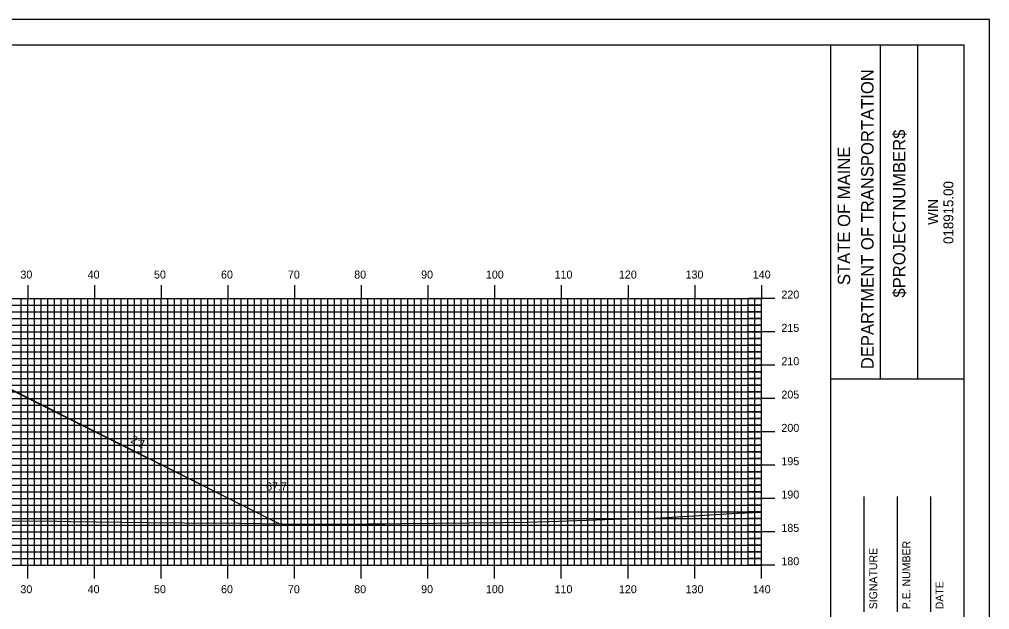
# Model space of a CAD drawing. Extents: x 1810193 to 1810536, y 442591 to 442811.
# Drawn here: x 1810387.6 to 1810533.1, y 442722 to 442810.5 of the extents above; entities that cross this region are included whole.
import ezdxf

# ---------------------------------------------------------------- set-up
doc = ezdxf.new("R2010")
doc.units = 0
for name, color, linetype in [('ANNOTATION', 7, 'Continuous'), ('BORDER', 7, 'Continuous'), ('D_Roadway_Centerline', 7, 'Continuous'), ('D_Roadway_SlopeLines', 7, 'Continuous'), ('D_Text_Standard', 7, 'Continuous'), ('H_V ANNOTATION', 7, 'Continuous'), ('MAJOR', 7, 'Continuous'), ('MINOR', 7, 'Continuous'), ('PLOT BOUNDARY', 7, 'Continuous'), ('S_Roadway_Centerline', 7, 'Continuous')]:
    doc.layers.add(name, color=color, linetype=linetype)

msp = doc.modelspace()

# ---------------------------------------------------------------- linework, layer by layer
at = {"layer": 'BORDER'}
for p, q in [((1810509.26, 442596.67), (1810509.26, 442806.67)), ((1810516.72, 442756.66), (1810516.72, 442806.66)), ((1810522.31, 442756.66), (1810522.31, 442806.66)), ((1810509.27, 442756.65), (1810529.26, 442756.65)), ((1810514.26, 442721.67), (1810514.26, 442738.97)), ((1810519.26, 442721.67), (1810519.26, 442738.97)), ((1810524.26, 442721.67), (1810524.26, 442738.97))]:
    msp.add_line(p, q, dxfattribs=at)
msp.add_lwpolyline([(1810209.26, 442596.67), (1810529.26, 442596.67), (1810529.26, 442806.67), (1810209.26, 442806.67)], close=True, dxfattribs=at)
at = {"layer": 'D_Roadway_Centerline'}
msp.add_lwpolyline([(1810289.54, 442735.57), (1810330.66, 442756.12), (1810335.86, 442758.73), (1810338.86, 442758.79), (1810346.86, 442758.95), (1810358.86, 442758.37), (1810370.86, 442757.79), (1810378.86, 442757.41), (1810381.86, 442757.27), (1810387.39, 442754.5), (1810426.61, 442734.89)], dxfattribs=at)
at = {"layer": 'D_Roadway_SlopeLines'}
msp.add_lwpolyline([(1810381.86, 442757.27), (1810426.61, 442734.89)], dxfattribs=at)
at = {"layer": 'MAJOR'}
for p, q in [((1810388.86, 442770.67), (1810388.86, 442768.67)), ((1810398.86, 442770.67), (1810398.86, 442768.67)), ((1810408.86, 442770.67), (1810408.86, 442768.67)), ((1810418.86, 442770.67), (1810418.86, 442768.67)), ((1810428.86, 442770.67), (1810428.86, 442768.67)), ((1810438.86, 442770.67), (1810438.86, 442768.67)), ((1810448.86, 442770.67), (1810448.86, 442768.67)), ((1810458.86, 442770.67), (1810458.86, 442768.67)), ((1810468.86, 442770.67), (1810468.86, 442768.67)), ((1810478.86, 442770.67), (1810478.86, 442768.67)), ((1810488.86, 442770.67), (1810488.86, 442768.67)), ((1810498.86, 442770.67), (1810498.86, 442768.67)), ((1810218.86, 442768.67), (1810498.86, 442768.67)), ((1810218.86, 442768.67), (1810498.86, 442768.67)), ((1810388.86, 442728.67), (1810388.86, 442768.67)), ((1810398.86, 442728.67), (1810398.86, 442768.67)), ((1810408.86, 442728.67), (1810408.86, 442768.67)), ((1810418.86, 442728.67), (1810418.86, 442768.67)), ((1810428.86, 442728.67), (1810428.86, 442768.67)), ((1810438.86, 442728.67), (1810438.86, 442768.67)), ((1810448.86, 442728.67), (1810448.86, 442768.67)), ((1810458.86, 442728.67), (1810458.86, 442768.67)), ((1810468.86, 442728.67), (1810468.86, 442768.67)), ((1810478.86, 442728.67), (1810478.86, 442768.67)), ((1810488.86, 442728.67), (1810488.86, 442768.67)), ((1810500.87, 442768.67), (1810496.86, 442768.67)), ((1810498.86, 442728.67), (1810498.86, 442768.67)), ((1810498.86, 442728.67), (1810498.86, 442768.67)), ((1810218.86, 442763.67), (1810498.86, 442763.67)), ((1810500.87, 442763.67), (1810496.86, 442763.67)), ((1810218.86, 442758.67), (1810498.86, 442758.67)), ((1810500.87, 442758.67), (1810496.86, 442758.67)), ((1810218.86, 442753.67), (1810498.86, 442753.67)), ((1810500.87, 442753.67), (1810496.86, 442753.67)), ((1810218.86, 442748.67), (1810498.86, 442748.67)), ((1810500.87, 442748.67), (1810496.86, 442748.67)), ((1810218.86, 442743.67), (1810498.86, 442743.67)), ((1810500.87, 442743.67), (1810496.86, 442743.67)), ((1810218.86, 442738.67), (1810498.86, 442738.67)), ((1810500.87, 442738.67), (1810496.86, 442738.67)), ((1810218.86, 442733.67), (1810498.86, 442733.67)), ((1810500.87, 442733.67), (1810496.86, 442733.67)), ((1810218.86, 442728.67), (1810498.86, 442728.67)), ((1810218.86, 442728.67), (1810498.86, 442728.67)), ((1810388.86, 442726.66), (1810388.86, 442728.67)), ((1810398.86, 442726.66), (1810398.86, 442728.67)), ((1810408.86, 442726.66), (1810408.86, 442728.67)), ((1810418.86, 442726.66), (1810418.86, 442728.67)), ((1810428.86, 442726.66), (1810428.86, 442728.67)), ((1810438.86, 442726.66), (1810438.86, 442728.67)), ((1810448.86, 442726.66), (1810448.86, 442728.67)), ((1810458.86, 442726.66), (1810458.86, 442728.67)), ((1810468.86, 442726.66), (1810468.86, 442728.67)), ((1810478.86, 442726.66), (1810478.86, 442728.67)), ((1810488.86, 442726.66), (1810488.86, 442728.67)), ((1810500.87, 442728.67), (1810496.86, 442728.67)), ((1810498.86, 442726.66), (1810498.86, 442728.67))]:
    msp.add_line(p, q, dxfattribs=at)
at = {"layer": 'MINOR'}
for p, q in [((1810387.86, 442728.67), (1810387.86, 442768.67)), ((1810389.86, 442728.67), (1810389.86, 442768.67)), ((1810390.86, 442728.67), (1810390.86, 442768.67)), ((1810391.86, 442728.67), (1810391.86, 442768.67)), ((1810392.86, 442728.67), (1810392.86, 442768.67)), ((1810393.86, 442728.67), (1810393.86, 442768.67)), ((1810394.86, 442728.67), (1810394.86, 442768.67)), ((1810395.86, 442728.67), (1810395.86, 442768.67)), ((1810396.86, 442728.67), (1810396.86, 442768.67)), ((1810397.86, 442728.67), (1810397.86, 442768.67)), ((1810399.86, 442728.67), (1810399.86, 442768.67)), ((1810400.86, 442728.67), (1810400.86, 442768.67)), ((1810401.86, 442728.67), (1810401.86, 442768.67)), ((1810402.86, 442728.67), (1810402.86, 442768.67)), ((1810403.86, 442728.67), (1810403.86, 442768.67)), ((1810404.86, 442728.67), (1810404.86, 442768.67)), ((1810405.86, 442728.67), (1810405.86, 442768.67)), ((1810406.86, 442728.67), (1810406.86, 442768.67)), ((1810407.86, 442728.67), (1810407.86, 442768.67)), ((1810409.86, 442728.67), (1810409.86, 442768.67)), ((1810410.86, 442728.67), (1810410.86, 442768.67)), ((1810411.86, 442728.67), (1810411.86, 442768.67)), ((1810412.86, 442728.67), (1810412.86, 442768.67)), ((1810413.86, 442728.67), (1810413.86, 442768.67)), ((1810414.86, 442728.67), (1810414.86, 442768.67)), ((1810415.86, 442728.67), (1810415.86, 442768.67)), ((1810416.86, 442728.67), (1810416.86, 442768.67)), ((1810417.86, 442728.67), (1810417.86, 442768.67)), ((1810419.86, 442728.67), (1810419.86, 442768.67)), ((1810420.86, 442728.67), (1810420.86, 442768.67)), ((1810421.86, 442728.67), (1810421.86, 442768.67)), ((1810422.86, 442728.67), (1810422.86, 442768.67)), ((1810423.86, 442728.67), (1810423.86, 442768.67)), ((1810424.86, 442728.67), (1810424.86, 442768.67)), ((1810425.86, 442728.67), (1810425.86, 442768.67)), ((1810426.86, 442728.67), (1810426.86, 442768.67)), ((1810427.86, 442728.67), (1810427.86, 442768.67)), ((1810429.86, 442728.67), (1810429.86, 442768.67)), ((1810430.86, 442728.67), (1810430.86, 442768.67)), ((1810431.86, 442728.67), (1810431.86, 442768.67)), ((1810432.86, 442728.67), (1810432.86, 442768.67)), ((1810433.86, 442728.67), (1810433.86, 442768.67)), ((1810434.86, 442728.67), (1810434.86, 442768.67)), ((1810435.86, 442728.67), (1810435.86, 442768.67)), ((1810436.86, 442728.67), (1810436.86, 442768.67)), ((1810437.86, 442728.67), (1810437.86, 442768.67)), ((1810439.86, 442728.67), (1810439.86, 442768.67)), ((1810440.86, 442728.67), (1810440.86, 442768.67)), ((1810441.86, 442728.67), (1810441.86, 442768.67)), ((1810442.86, 442728.67), (1810442.86, 442768.67)), ((1810443.86, 442728.67), (1810443.86, 442768.67)), ((1810444.86, 442728.67), (1810444.86, 442768.67)), ((1810445.86, 442728.67), (1810445.86, 442768.67)), ((1810446.86, 442728.67), (1810446.86, 442768.67)), ((1810447.86, 442728.67), (1810447.86, 442768.67)), ((1810449.86, 442728.67), (1810449.86, 442768.67)), ((1810450.86, 442728.67), (1810450.86, 442768.67)), ((1810451.86, 442728.67), (1810451.86, 442768.67)), ((1810452.86, 442728.67), (1810452.86, 442768.67)), ((1810453.86, 442728.67), (1810453.86, 442768.67)), ((1810454.86, 442728.67), (1810454.86, 442768.67)), ((1810455.86, 442728.67), (1810455.86, 442768.67)), ((1810456.86, 442728.67), (1810456.86, 442768.67)), ((1810457.86, 442728.67), (1810457.86, 442768.67)), ((1810459.86, 442728.67), (1810459.86, 442768.67)), ((1810460.86, 442728.67), (1810460.86, 442768.67)), ((1810461.86, 442728.67), (1810461.86, 442768.67)), ((1810462.86, 442728.67), (1810462.86, 442768.67)), ((1810463.86, 442728.67), (1810463.86, 442768.67)), ((1810464.86, 442728.67), (1810464.86, 442768.67)), ((1810465.86, 442728.67), (1810465.86, 442768.67)), ((1810466.86, 442728.67), (1810466.86, 442768.67)), ((1810467.86, 442728.67), (1810467.86, 442768.67)), ((1810469.86, 442728.67), (1810469.86, 442768.67)), ((1810470.86, 442728.67), (1810470.86, 442768.67)), ((1810471.86, 442728.67), (1810471.86, 442768.67)), ((1810472.86, 442728.67), (1810472.86, 442768.67)), ((1810473.86, 442728.67), (1810473.86, 442768.67)), ((1810474.86, 442728.67), (1810474.86, 442768.67)), ((1810475.86, 442728.67), (1810475.86, 442768.67)), ((1810476.86, 442728.67), (1810476.86, 442768.67)), ((1810477.86, 442728.67), (1810477.86, 442768.67)), ((1810479.86, 442728.67), (1810479.86, 442768.67)), ((1810480.86, 442728.67), (1810480.86, 442768.67)), ((1810481.86, 442728.67), (1810481.86, 442768.67)), ((1810482.86, 442728.67), (1810482.86, 442768.67)), ((1810483.86, 442728.67), (1810483.86, 442768.67)), ((1810484.86, 442728.67), (1810484.86, 442768.67)), ((1810485.86, 442728.67), (1810485.86, 442768.67)), ((1810486.86, 442728.67), (1810486.86, 442768.67)), ((1810487.86, 442728.67), (1810487.86, 442768.67)), ((1810489.86, 442728.67), (1810489.86, 442768.67)), ((1810490.86, 442728.67), (1810490.86, 442768.67)), ((1810491.86, 442728.67), (1810491.86, 442768.67)), ((1810492.86, 442728.67), (1810492.86, 442768.67)), ((1810493.86, 442728.67), (1810493.86, 442768.67)), ((1810494.86, 442728.67), (1810494.86, 442768.67)), ((1810495.86, 442728.67), (1810495.86, 442768.67)), ((1810496.86, 442728.67), (1810496.86, 442768.67)), ((1810497.86, 442728.67), (1810497.86, 442768.67)), ((1810218.86, 442767.67), (1810498.86, 442767.67)), ((1810498.86, 442767.67), (1810496.86, 442767.67)), ((1810218.86, 442766.67), (1810498.86, 442766.67)), ((1810218.86, 442765.67), (1810498.86, 442765.67)), ((1810498.86, 442766.67), (1810496.86, 442766.67)), ((1810498.86, 442765.67), (1810496.86, 442765.67)), ((1810218.86, 442764.67), (1810498.86, 442764.67)), ((1810498.86, 442764.67), (1810496.86, 442764.67)), ((1810218.86, 442762.67), (1810498.86, 442762.67)), ((1810498.86, 442762.67), (1810496.86, 442762.67)), ((1810218.86, 442761.67), (1810498.86, 442761.67)), ((1810498.86, 442761.67), (1810496.86, 442761.67)), ((1810218.86, 442760.67), (1810498.86, 442760.67)), ((1810498.86, 442760.67), (1810496.86, 442760.67)), ((1810218.86, 442759.67), (1810498.86, 442759.67)), ((1810498.86, 442759.67), (1810496.86, 442759.67)), ((1810218.86, 442757.67), (1810498.86, 442757.67)), ((1810498.86, 442757.67), (1810496.86, 442757.67)), ((1810218.86, 442756.67), (1810498.86, 442756.67)), ((1810218.86, 442755.67), (1810498.86, 442755.67)), ((1810498.86, 442756.67), (1810496.86, 442756.67)), ((1810498.86, 442755.67), (1810496.86, 442755.67)), ((1810218.86, 442754.67), (1810498.86, 442754.67)), ((1810498.86, 442754.67), (1810496.86, 442754.67)), ((1810218.86, 442752.67), (1810498.86, 442752.67)), ((1810498.86, 442752.67), (1810496.86, 442752.67)), ((1810218.86, 442751.67), (1810498.86, 442751.67)), ((1810498.86, 442751.67), (1810496.86, 442751.67)), ((1810218.86, 442750.67), (1810498.86, 442750.67)), ((1810218.86, 442749.67), (1810498.86, 442749.67)), ((1810498.86, 442750.67), (1810496.86, 442750.67)), ((1810498.86, 442749.67), (1810496.86, 442749.67)), ((1810218.86, 442747.67), (1810498.86, 442747.67)), ((1810218.86, 442746.67), (1810498.86, 442746.67)), ((1810498.86, 442747.67), (1810496.86, 442747.67)), ((1810498.86, 442746.67), (1810496.86, 442746.67)), ((1810218.86, 442745.67), (1810498.86, 442745.67)), ((1810498.86, 442745.67), (1810496.86, 442745.67)), ((1810218.86, 442744.67), (1810498.86, 442744.67)), ((1810498.86, 442744.67), (1810496.86, 442744.67)), ((1810218.86, 442742.67), (1810498.86, 442742.67)), ((1810498.86, 442742.67), (1810496.86, 442742.67)), ((1810218.86, 442741.67), (1810498.86, 442741.67)), ((1810498.86, 442741.67), (1810496.86, 442741.67)), ((1810218.86, 442740.67), (1810498.86, 442740.67)), ((1810218.86, 442739.67), (1810498.86, 442739.67)), ((1810498.86, 442740.67), (1810496.86, 442740.67)), ((1810498.86, 442739.67), (1810496.86, 442739.67)), ((1810218.86, 442737.67), (1810498.86, 442737.67)), ((1810218.86, 442736.67), (1810498.86, 442736.67)), ((1810498.86, 442737.67), (1810496.86, 442737.67)), ((1810498.86, 442736.67), (1810496.86, 442736.67)), ((1810218.86, 442735.67), (1810498.86, 442735.67)), ((1810498.86, 442735.67), (1810496.86, 442735.67)), ((1810218.86, 442734.67), (1810498.86, 442734.67)), ((1810498.86, 442734.67), (1810496.86, 442734.67)), ((1810218.86, 442732.67), (1810498.86, 442732.67)), ((1810498.86, 442732.67), (1810496.86, 442732.67)), ((1810218.86, 442731.67), (1810498.86, 442731.67)), ((1810218.86, 442730.67), (1810498.86, 442730.67)), ((1810498.86, 442731.67), (1810496.86, 442731.67)), ((1810498.86, 442730.67), (1810496.86, 442730.67)), ((1810218.86, 442729.67), (1810498.86, 442729.67)), ((1810498.86, 442729.67), (1810496.86, 442729.67))]:
    msp.add_line(p, q, dxfattribs=at)
at = {"layer": 'PLOT BOUNDARY'}
msp.add_lwpolyline([(1810193.08, 442590.55), (1810533.08, 442590.55), (1810533.08, 442810.55), (1810193.08, 442810.55)], close=True, dxfattribs=at)
at = {"layer": 'S_Roadway_Centerline'}
msp.add_lwpolyline([(1810372.66, 442735.45), (1810393.27, 442735.26), (1810395.17, 442735.25), (1810395.31, 442735.24), (1810406.69, 442735.1), (1810417.98, 442734.99), (1810419.4, 442735.01), (1810420.68, 442734.96), (1810430.26, 442734.85), (1810439.96, 442734.87), (1810442.38, 442734.9), (1810444.96, 442734.94), (1810460.1, 442735.08), (1810463.81, 442735.11), (1810468.49, 442735.3), (1810476.8, 442735.57), (1810483.01, 442735.75), (1810495.21, 442736.47), (1810498.86, 442736.61)], dxfattribs=at)

# ---------------------------------------------------------------- texts
at = {"layer": 'ANNOTATION'}
msp.add_text('2:1', height=1.2, rotation=333.4349, dxfattribs=at).set_placement((1810404.17, 442747.15))
at = {"layer": 'BORDER'}
for s, height, p in [('DEPARTMENT OF TRANSPORTATION', 1.8635, (1810515.68, 442758.08)), ('$PROJECTNUMBER$', 1.8635, (1810520.45, 442768.82)), ('STATE OF MAINE', 1.8635, (1810512.17, 442770.69)), ('018915.00', 1.491, (1810527.65, 442776.86)), ('WIN', 1.491, (1810525.34, 442779.73)), ('P.E. NUMBER', 1.1811, (1810521.19, 442722.06)), ('SIGNATURE', 1.181, (1810516.22, 442722.06)), ('DATE', 1.181, (1810526.15, 442722.06))]:
    msp.add_text(s, height=height, rotation=90, dxfattribs=at).set_placement(p)
at = {"layer": 'D_Text_Standard'}
msp.add_text("67.7'", height=1.2, dxfattribs=at).set_placement((1810424.6, 442739.88))
at = {"layer": 'H_V ANNOTATION'}
for s, p in [('30', (1810387.76, 442771.67)), ('40', (1810397.84, 442771.67)), ('50', (1810407.79, 442771.67)), ('60', (1810417.84, 442771.67)), ('70', (1810427.87, 442771.67)), ('80', (1810437.81, 442771.67)), ('90', (1810447.84, 442771.67)), ('100', (1810457.55, 442771.67)), ('110', (1810467.85, 442771.67)), ('120', (1810477.5, 442771.67)), ('130', (1810487.49, 442771.67)), ('140', (1810497.57, 442771.67)), ('220', (1810501.86, 442768.67)), ('215', (1810501.86, 442763.67)), ('210', (1810501.86, 442758.67)), ('205', (1810501.86, 442753.67)), ('200', (1810501.86, 442748.67)), ('195', (1810501.86, 442743.67)), ('190', (1810501.86, 442738.67)), ('185', (1810501.86, 442733.67)), ('180', (1810501.86, 442728.67)), ('30', (1810387.76, 442724.47)), ('40', (1810397.84, 442724.47)), ('50', (1810407.79, 442724.47)), ('60', (1810417.84, 442724.47)), ('70', (1810427.87, 442724.47)), ('80', (1810437.81, 442724.47)), ('90', (1810447.84, 442724.47)), ('100', (1810457.55, 442724.47)), ('110', (1810467.85, 442724.47)), ('120', (1810477.5, 442724.47)), ('130', (1810487.49, 442724.47)), ('140', (1810497.57, 442724.47))]:
    msp.add_text(s, height=1.2, dxfattribs=at).set_placement(p)

doc.saveas('drawing.dxf')
